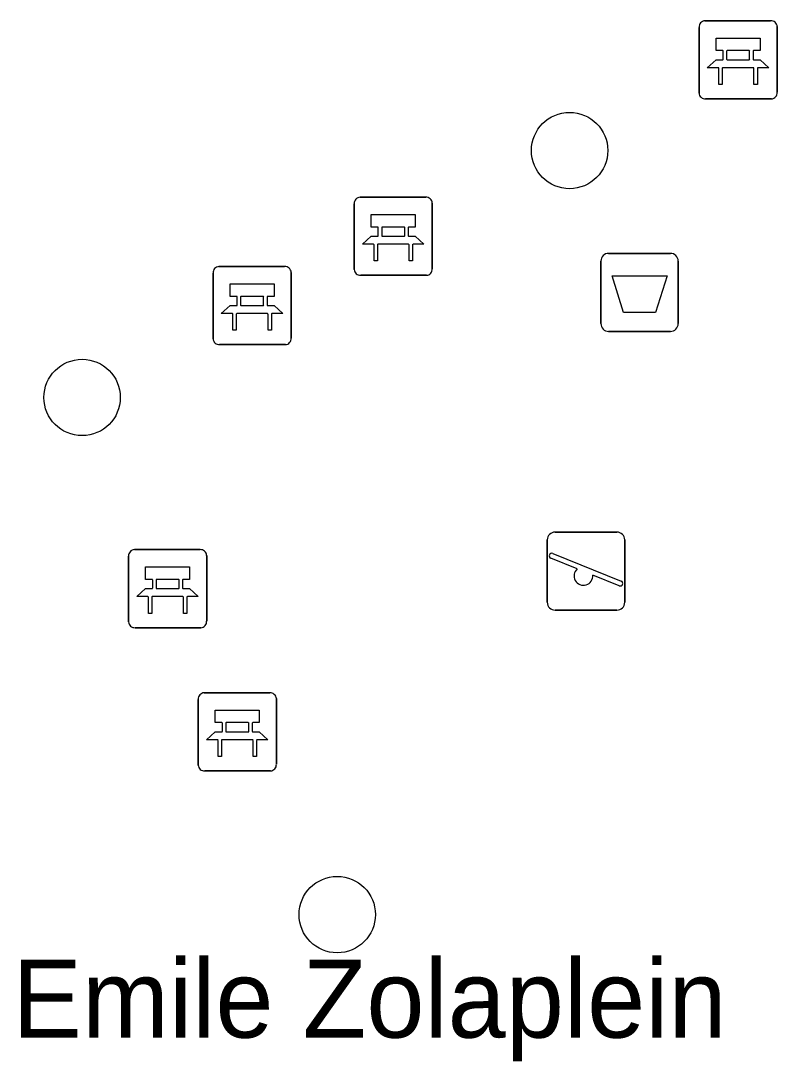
# Model space of a CAD drawing. Extents: x 160455 to 162082, y 388339 to 389736.
# Drawn here: x 160721.81 to 160731.49, y 389025.44 to 389038.77 of the extents above; entities that cross this region are included whole.
import ezdxf

# ---------------------------------------------------------------- set-up
doc = ezdxf.new("R2010")
doc.units = 0
for name, color, linetype in [('IMGEO_Afvalbak', 7, 'Continuous'), ('IMGEO_Bank', 7, 'Continuous'), ('IMGEO_Boom', 7, 'Continuous'), ('IMGEO_Openbare_ruimte_label', 7, 'Continuous'), ('IMGEO_Speelvoorziening', 7, 'Continuous')]:
    doc.layers.add(name, color=color, linetype=linetype)

msp = doc.modelspace()

# ---------------------------------------------------------------- linework, layer by layer
at = {"layer": 'IMGEO_Afvalbak'}
for p, q in [((160729.331, 389035.791), (160730.121, 389035.791)), ((160730.121, 389035.791), (160729.331, 389035.791)), ((160729.231, 389034.891), (160729.231, 389035.691)), ((160729.231, 389035.691), (160729.231, 389034.891)), ((160730.221, 389035.691), (160730.221, 389034.891)), ((160730.221, 389034.891), (160730.221, 389035.691)), ((160730.121, 389034.791), (160729.331, 389034.791)), ((160729.331, 389034.791), (160730.121, 389034.791))]:
    msp.add_line(p, q, dxfattribs=at)
msp.add_lwpolyline([(160729.374, 389035.505), (160730.078, 389035.505), (160729.929, 389035.035), (160729.523, 389035.035), (160729.374, 389035.505)], dxfattribs=at)
for centre, start, end in [((160729.331, 389035.691), 90, 180), ((160729.331, 389035.691), 90, 180), ((160730.121, 389035.691), 0, 90), ((160730.121, 389035.691), 360, 90), ((160729.331, 389034.891), 180, 270), ((160729.331, 389034.891), 180, 270), ((160730.121, 389034.891), 270, 0), ((160730.121, 389034.891), 270, 0)]:
    msp.add_arc(centre, 0.1, start, end, dxfattribs=at)
at = {"layer": 'IMGEO_Bank'}
for p, q in [((160730.488, 389037.845), (160730.488, 389038.686)), ((160730.488, 389038.686), (160730.488, 389037.845)), ((160730.563, 389038.77), (160731.404, 389038.77)), ((160731.404, 389038.77), (160730.563, 389038.77)), ((160731.488, 389038.695), (160731.488, 389037.854)), ((160731.488, 389037.854), (160731.488, 389038.695)), ((160730.797, 389038.276), (160730.797, 389038.382)), ((160730.841, 389038.382), (160730.841, 389038.276)), ((160731.129, 389038.388), (160730.847, 389038.388)), ((160731.135, 389038.276), (160731.135, 389038.382)), ((160731.179, 389038.382), (160731.179, 389038.276)), ((160731.185, 389038.168), (160730.792, 389038.168)), ((160730.847, 389038.27), (160731.129, 389038.27)), ((160731.413, 389037.77), (160730.572, 389037.77)), ((160730.572, 389037.77), (160731.413, 389037.77)), ((160726.074, 389035.585), (160726.074, 389036.426)), ((160726.074, 389036.426), (160726.074, 389035.585)), ((160726.149, 389036.51), (160726.99, 389036.51)), ((160726.99, 389036.51), (160726.149, 389036.51)), ((160727.074, 389036.435), (160727.074, 389035.594)), ((160727.074, 389035.594), (160727.074, 389036.435)), ((160726.383, 389036.016), (160726.383, 389036.122)), ((160726.427, 389036.122), (160726.427, 389036.016)), ((160726.715, 389036.128), (160726.433, 389036.128)), ((160726.433, 389036.01), (160726.715, 389036.01)), ((160726.721, 389036.016), (160726.721, 389036.122)), ((160726.765, 389036.122), (160726.765, 389036.016)), ((160726.771, 389035.908), (160726.378, 389035.908)), ((160724.343, 389035.622), (160725.184, 389035.622)), ((160725.184, 389035.622), (160724.343, 389035.622)), ((160724.268, 389034.697), (160724.268, 389035.538)), ((160724.268, 389035.538), (160724.268, 389034.697)), ((160725.268, 389035.547), (160725.268, 389034.706)), ((160725.268, 389034.706), (160725.268, 389035.547)), ((160726.999, 389035.51), (160726.158, 389035.51)), ((160726.158, 389035.51), (160726.999, 389035.51)), ((160724.577, 389035.128), (160724.577, 389035.234)), ((160724.621, 389035.234), (160724.621, 389035.128)), ((160724.909, 389035.24), (160724.627, 389035.24)), ((160724.915, 389035.128), (160724.915, 389035.234)), ((160724.959, 389035.234), (160724.959, 389035.128)), ((160724.627, 389035.122), (160724.909, 389035.122)), ((160724.965, 389035.02), (160724.572, 389035.02)), ((160725.193, 389034.622), (160724.352, 389034.622)), ((160724.352, 389034.622), (160725.193, 389034.622)), ((160723.186, 389031.071), (160723.186, 389031.912)), ((160723.186, 389031.912), (160723.186, 389031.071)), ((160723.261, 389031.996), (160724.102, 389031.996)), ((160724.102, 389031.996), (160723.261, 389031.996)), ((160724.186, 389031.921), (160724.186, 389031.08)), ((160724.186, 389031.08), (160724.186, 389031.921)), ((160723.827, 389031.614), (160723.545, 389031.614)), ((160723.495, 389031.502), (160723.495, 389031.608)), ((160723.539, 389031.608), (160723.539, 389031.502)), ((160723.545, 389031.496), (160723.827, 389031.496)), ((160723.833, 389031.502), (160723.833, 389031.608)), ((160723.877, 389031.608), (160723.877, 389031.502)), ((160723.883, 389031.394), (160723.49, 389031.394)), ((160724.111, 389030.996), (160723.27, 389030.996)), ((160723.27, 389030.996), (160724.111, 389030.996)), ((160724.153, 389030.162), (160724.994, 389030.162)), ((160724.994, 389030.162), (160724.153, 389030.162)), ((160724.078, 389029.237), (160724.078, 389030.078)), ((160724.078, 389030.078), (160724.078, 389029.237)), ((160725.078, 389030.087), (160725.078, 389029.246)), ((160725.078, 389029.246), (160725.078, 389030.087)), ((160724.387, 389029.668), (160724.387, 389029.774)), ((160724.431, 389029.774), (160724.431, 389029.668)), ((160724.719, 389029.78), (160724.437, 389029.78)), ((160724.725, 389029.668), (160724.725, 389029.774)), ((160724.769, 389029.774), (160724.769, 389029.668)), ((160724.437, 389029.662), (160724.719, 389029.662)), ((160724.775, 389029.56), (160724.382, 389029.56)), ((160725.003, 389029.162), (160724.162, 389029.162)), ((160724.162, 389029.162), (160725.003, 389029.162))]:
    msp.add_line(p, q, dxfattribs=at)
for points in [[(160730.791, 389038.388), (160730.705, 389038.388), (160730.705, 389038.549), (160731.268, 389038.549), (160731.268, 389038.388), (160731.185, 389038.388)], [(160730.735, 389038.168), (160730.593, 389038.168), (160730.705, 389038.27), (160730.791, 389038.27)], [(160730.785, 389038.161), (160730.785, 389037.954), (160730.742, 389037.954), (160730.742, 389038.161)], [(160731.185, 389038.27), (160731.268, 389038.27), (160731.38, 389038.168), (160731.241, 389038.168)], [(160731.235, 389038.161), (160731.235, 389037.954), (160731.191, 389037.954), (160731.191, 389038.161)], [(160726.377, 389036.128), (160726.291, 389036.128), (160726.291, 389036.289), (160726.854, 389036.289), (160726.854, 389036.128), (160726.771, 389036.128)], [(160726.321, 389035.908), (160726.179, 389035.908), (160726.291, 389036.01), (160726.377, 389036.01)], [(160726.771, 389036.01), (160726.854, 389036.01), (160726.966, 389035.908), (160726.827, 389035.908)], [(160726.371, 389035.901), (160726.371, 389035.694), (160726.328, 389035.694), (160726.328, 389035.901)], [(160726.821, 389035.901), (160726.821, 389035.694), (160726.777, 389035.694), (160726.777, 389035.901)], [(160724.571, 389035.24), (160724.485, 389035.24), (160724.485, 389035.401), (160725.048, 389035.401), (160725.048, 389035.24), (160724.965, 389035.24)], [(160724.515, 389035.02), (160724.373, 389035.02), (160724.485, 389035.122), (160724.571, 389035.122)], [(160724.965, 389035.122), (160725.048, 389035.122), (160725.16, 389035.02), (160725.021, 389035.02)], [(160724.565, 389035.013), (160724.565, 389034.806), (160724.522, 389034.806), (160724.522, 389035.013)], [(160725.015, 389035.013), (160725.015, 389034.806), (160724.971, 389034.806), (160724.971, 389035.013)], [(160723.489, 389031.614), (160723.403, 389031.614), (160723.403, 389031.775), (160723.966, 389031.775), (160723.966, 389031.614), (160723.883, 389031.614)], [(160723.433, 389031.394), (160723.291, 389031.394), (160723.403, 389031.496), (160723.489, 389031.496)], [(160723.883, 389031.496), (160723.966, 389031.496), (160724.078, 389031.394), (160723.939, 389031.394)], [(160723.483, 389031.387), (160723.483, 389031.18), (160723.44, 389031.18), (160723.44, 389031.387)], [(160723.933, 389031.387), (160723.933, 389031.18), (160723.889, 389031.18), (160723.889, 389031.387)], [(160724.381, 389029.78), (160724.295, 389029.78), (160724.295, 389029.941), (160724.858, 389029.941), (160724.858, 389029.78), (160724.775, 389029.78)], [(160724.325, 389029.56), (160724.183, 389029.56), (160724.295, 389029.662), (160724.381, 389029.662)], [(160724.775, 389029.662), (160724.858, 389029.662), (160724.97, 389029.56), (160724.831, 389029.56)], [(160724.375, 389029.553), (160724.375, 389029.346), (160724.332, 389029.346), (160724.332, 389029.553)], [(160724.825, 389029.553), (160724.825, 389029.346), (160724.781, 389029.346), (160724.781, 389029.553)]]:
    msp.add_lwpolyline(points, dxfattribs=at)
for centre, radius, start, end in [((160730.566, 389038.692), 0.0779, 92.4484, 184.2845), ((160730.566, 389038.692), 0.0779, 92.4484, 184.2845), ((160731.41, 389038.692), 0.0779, 2.4484, 94.2845), ((160731.41, 389038.692), 0.0779, 2.4484, 94.2845), ((160730.79, 389038.381), 0.00671, 2.8957, 87.1043), ((160730.79, 389038.277), 0.00671, 272.8957, 357.1043), ((160730.847, 389038.381), 0.00671, 92.8957, 177.1043), ((160730.847, 389038.277), 0.00671, 182.8957, 267.1043), ((160731.129, 389038.381), 0.00671, 2.8957, 87.1043), ((160731.129, 389038.277), 0.00671, 272.8957, 357.1043), ((160731.186, 389038.381), 0.00671, 92.8957, 177.1043), ((160731.186, 389038.277), 0.00671, 182.8957, 267.1043), ((160730.735, 389038.161), 0.00671, 2.8957, 87.1043), ((160730.792, 389038.161), 0.00671, 92.8957, 177.1043), ((160731.184, 389038.161), 0.00671, 2.8957, 87.1043), ((160731.241, 389038.161), 0.00671, 92.8957, 177.1043), ((160730.566, 389037.848), 0.0779, 182.4484, 274.2845), ((160730.566, 389037.848), 0.0779, 182.4484, 274.2845), ((160731.41, 389037.848), 0.0779, 272.4484, 4.2845), ((160731.41, 389037.848), 0.0779, 272.4484, 4.2845), ((160726.152, 389036.432), 0.0779, 92.4484, 184.2845), ((160726.152, 389036.432), 0.0779, 92.4484, 184.2845), ((160726.996, 389036.432), 0.0779, 2.4484, 94.2845), ((160726.996, 389036.432), 0.0779, 2.4484, 94.2845), ((160726.376, 389036.121), 0.00671, 2.8957, 87.1043), ((160726.376, 389036.017), 0.00671, 272.8957, 357.1043), ((160726.433, 389036.121), 0.00671, 92.8957, 177.1043), ((160726.433, 389036.017), 0.00671, 182.8957, 267.1043), ((160726.715, 389036.121), 0.00671, 2.8957, 87.1043), ((160726.715, 389036.017), 0.00671, 272.8957, 357.1043), ((160726.772, 389036.121), 0.00671, 92.8957, 177.1043), ((160726.772, 389036.017), 0.00671, 182.8957, 267.1043), ((160726.321, 389035.901), 0.00671, 2.8957, 87.1043), ((160726.378, 389035.901), 0.00671, 92.8957, 177.1043), ((160726.77, 389035.901), 0.00671, 2.8957, 87.1043), ((160726.827, 389035.901), 0.00671, 92.8957, 177.1043), ((160724.346, 389035.544), 0.0779, 92.4484, 184.2845), ((160724.346, 389035.544), 0.0779, 92.4484, 184.2845), ((160725.19, 389035.544), 0.0779, 2.4484, 94.2845), ((160725.19, 389035.544), 0.0779, 2.4484, 94.2845), ((160726.152, 389035.588), 0.0779, 182.4484, 274.2845), ((160726.152, 389035.588), 0.0779, 182.4484, 274.2845), ((160726.996, 389035.588), 0.0779, 272.4484, 4.2845), ((160726.996, 389035.588), 0.0779, 272.4484, 4.2845), ((160724.57, 389035.233), 0.00671, 2.8957, 87.1043), ((160724.627, 389035.233), 0.00671, 92.8957, 177.1043), ((160724.909, 389035.233), 0.00671, 2.8957, 87.1043), ((160724.966, 389035.233), 0.00671, 92.8957, 177.1043), ((160724.57, 389035.129), 0.00671, 272.8957, 357.1043), ((160724.627, 389035.129), 0.00671, 182.8957, 267.1043), ((160724.909, 389035.129), 0.00671, 272.8957, 357.1043), ((160724.966, 389035.129), 0.00671, 182.8957, 267.1043), ((160724.515, 389035.013), 0.00671, 2.8957, 87.1043), ((160724.572, 389035.013), 0.00671, 92.8957, 177.1043), ((160724.964, 389035.013), 0.00671, 2.8957, 87.1043), ((160725.021, 389035.013), 0.00671, 92.8957, 177.1043), ((160724.346, 389034.7), 0.0779, 182.4484, 274.2845), ((160724.346, 389034.7), 0.0779, 182.4484, 274.2845), ((160725.19, 389034.7), 0.0779, 272.4484, 4.2845), ((160725.19, 389034.7), 0.0779, 272.4484, 4.2845), ((160723.264, 389031.918), 0.0779, 92.4484, 184.2845), ((160723.264, 389031.918), 0.0779, 92.4484, 184.2845), ((160724.108, 389031.918), 0.0779, 2.4484, 94.2845), ((160724.108, 389031.918), 0.0779, 2.4484, 94.2845), ((160723.488, 389031.607), 0.00671, 2.8957, 87.1043), ((160723.545, 389031.607), 0.00671, 92.8957, 177.1043), ((160723.827, 389031.607), 0.00671, 2.8957, 87.1043), ((160723.884, 389031.607), 0.00671, 92.8957, 177.1043), ((160723.488, 389031.503), 0.00671, 272.8957, 357.1043), ((160723.545, 389031.503), 0.00671, 182.8957, 267.1043), ((160723.827, 389031.503), 0.00671, 272.8957, 357.1043), ((160723.884, 389031.503), 0.00671, 182.8957, 267.1043), ((160723.433, 389031.387), 0.00671, 2.8957, 87.1043), ((160723.49, 389031.387), 0.00671, 92.8957, 177.1043), ((160723.882, 389031.387), 0.00671, 2.8957, 87.1043), ((160723.939, 389031.387), 0.00671, 92.8957, 177.1043), ((160724.108, 389031.074), 0.0779, 272.4484, 4.2845), ((160724.108, 389031.074), 0.0779, 272.4484, 4.2845), ((160723.264, 389031.074), 0.0779, 182.4484, 274.2845), ((160723.264, 389031.074), 0.0779, 182.4484, 274.2845), ((160724.156, 389030.084), 0.0779, 92.4484, 184.2845), ((160724.156, 389030.084), 0.0779, 92.4484, 184.2845), ((160725, 389030.084), 0.0779, 2.4484, 94.2845), ((160725, 389030.084), 0.0779, 2.4484, 94.2845), ((160724.38, 389029.773), 0.00671, 2.8957, 87.1043), ((160724.437, 389029.773), 0.00671, 92.8957, 177.1043), ((160724.719, 389029.773), 0.00671, 2.8957, 87.1043), ((160724.776, 389029.773), 0.00671, 92.8957, 177.1043), ((160724.38, 389029.669), 0.00671, 272.8957, 357.1043), ((160724.437, 389029.669), 0.00671, 182.8957, 267.1043), ((160724.719, 389029.669), 0.00671, 272.8957, 357.1043), ((160724.776, 389029.669), 0.00671, 182.8957, 267.1043), ((160724.325, 389029.553), 0.00671, 2.8957, 87.1043), ((160724.382, 389029.553), 0.00671, 92.8957, 177.1043), ((160724.774, 389029.553), 0.00671, 2.8957, 87.1043), ((160724.831, 389029.553), 0.00671, 92.8957, 177.1043), ((160724.156, 389029.24), 0.0779, 182.4484, 274.2845), ((160724.156, 389029.24), 0.0779, 182.4484, 274.2845), ((160725, 389029.24), 0.0779, 272.4484, 4.2845), ((160725, 389029.24), 0.0779, 272.4484, 4.2845)]:
    msp.add_arc(centre, radius, start, end, dxfattribs=at)
at = {"layer": 'IMGEO_Boom'}
for centre in [(160728.831, 389037.108), (160722.592, 389033.945), (160725.857, 389027.321)]:
    msp.add_circle(centre, 0.489, dxfattribs=at)
at = {"layer": 'IMGEO_Speelvoorziening'}
for p, q in [((160728.646, 389032.221), (160729.436, 389032.221)), ((160729.436, 389032.221), (160728.646, 389032.221)), ((160728.546, 389031.321), (160728.546, 389032.121)), ((160728.546, 389032.121), (160728.546, 389031.321)), ((160729.536, 389032.121), (160729.536, 389031.321)), ((160729.536, 389031.321), (160729.536, 389032.121)), ((160728.929, 389031.749), (160728.59, 389031.886)), ((160728.615, 389031.946), (160729.491, 389031.593)), ((160729.467, 389031.533), (160729.127, 389031.67)), ((160729.436, 389031.221), (160728.646, 389031.221)), ((160728.646, 389031.221), (160729.436, 389031.221))]:
    msp.add_line(p, q, dxfattribs=at)
for centre, radius, start, end in [((160728.646, 389032.121), 0.1, 90, 180), ((160728.646, 389032.121), 0.1, 90, 180), ((160729.436, 389032.121), 0.1, 0, 90), ((160729.436, 389032.121), 0.1, 360, 90), ((160728.603, 389031.916), 0.0327, 68.078, 248.078), ((160729.008, 389031.659), 0.12, 130.9928, 5.1632), ((160729.479, 389031.563), 0.0327, 248.078, 68.078), ((160728.646, 389031.321), 0.1, 180, 270), ((160728.646, 389031.321), 0.1, 180, 270), ((160729.436, 389031.321), 0.1, 270, 0), ((160729.436, 389031.321), 0.1, 270, 0)]:
    msp.add_arc(centre, radius, start, end, dxfattribs=at)

# ---------------------------------------------------------------- texts
at = {"layer": 'IMGEO_Openbare_ruimte_label'}
msp.add_text('Emile Zolaplein', height=1, dxfattribs=at).set_placement((160721.698, 389025.745))

doc.saveas('drawing.dxf')
